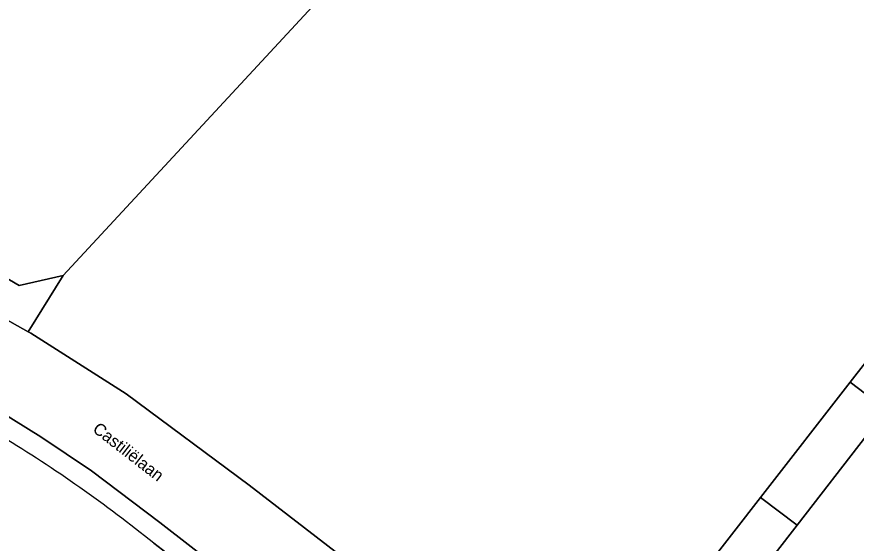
# Model space of a CAD drawing. Extents: x 159451 to 160664, y 388402 to 389723.
# Drawn here: x 160157.1 to 160226.5, y 389335.2 to 389378.7 of the extents above; entities that cross this region are included whole.
import ezdxf

# ---------------------------------------------------------------- set-up
doc = ezdxf.new("R2010")
doc.units = 0
for name, color, linetype in [('IMGEO_Erf', 7, 'Continuous'), ('IMGEO_Groenvoorziening', 7, 'Continuous'), ('IMGEO_Hek', 7, 'Continuous'), ('IMGEO_Openbare_ruimte_label', 7, 'Continuous'), ('IMGEO_Pand', 7, 'Continuous'), ('IMGEO_Rijbaan_lokaal_gesloten', 7, 'Continuous'), ('IMGEO_Voetpad_open', 7, 'Continuous')]:
    doc.layers.add(name, color=color, linetype=linetype)

msp = doc.modelspace()

# ---------------------------------------------------------------- linework, layer by layer
at = {"layer": 'IMGEO_Erf'}
msp.add_lwpolyline([(160227.35, 389344.083), (160221.58, 389336.65), (160214.309, 389327.282), (160216.954, 389325.219), (160212.581, 389319.604), (160206.952, 389323.994), (160206.897, 389324.038), (160205.223, 389321.905), (160205.887, 389321.394), (160222.965, 389308.25), (160226.576, 389313.019)], dxfattribs=at)
at = {"layer": 'IMGEO_Groenvoorziening'}
for points in [[(160039.736, 389411.806), (160043.519, 389377.125), (160045.569, 389377.185), (160095.565, 389378.647), (160130.286, 389372.303), (160147.497, 389362.17), (160157.284, 389356.446), (160160.932, 389357.287), (160193.043, 389391.963)], [(160193.043, 389391.963), (160160.932, 389357.287), (160158.016, 389352.63), (160158.238, 389352.505), (160166.141, 389347.496), (160176.29, 389339.963), (160199.403, 389322.122)], [(160206.952, 389323.994), (160218.568, 389338.933), (160225.978, 389348.463), (160233.375, 389357.976)], [(160221.208, 389296.259), (160220.228, 389294.868), (160218.806, 389296.075), (160218.402, 389295.619), (160215.327, 389298.05), (160215.702, 389298.491), (160170.928, 389333.22), (160168.404, 389335.154)]]:
    msp.add_lwpolyline(points, dxfattribs=at)
msp.add_lwpolyline([(160147.497, 389362.17), (160130.286, 389372.303), (160095.565, 389378.647), (160045.569, 389377.185), (160045.926, 389372.321), (160046.187, 389370.471), (160048, 389370.978), (160058.462, 389372.84), (160069.049, 389373.761), (160080.311, 389374.183), (160093.137, 389373.585), (160094.37, 389373.482), (160107.091, 389371.783), (160119.61, 389368.955), (160127.38, 389366.512), (160143.847, 389360.125), (160149.732, 389357.286), (160158.016, 389352.63), (160160.932, 389357.287), (160157.284, 389356.446)], close=True, dxfattribs=at)
msp.add_arc((160097.271, 389247.24), 113.087, 51.02304, 58.78252, dxfattribs=at)
at = {"layer": 'IMGEO_Hek'}
msp.add_lwpolyline([(160147.497, 389362.17), (160157.284, 389356.446), (160160.932, 389357.287)], dxfattribs=at)
at = {"layer": 'IMGEO_Pand'}
for points in [[(160233.602, 389352.12), (160236.032, 389350.278), (160238.691, 389353.723), (160238.8, 389353.864), (160236.382, 389355.697), (160233.375, 389357.976), (160225.978, 389348.463), (160228.984, 389346.184)], [(160227.35, 389344.083), (160228.984, 389346.184), (160225.978, 389348.463), (160218.568, 389338.933), (160221.58, 389336.65)], [(160221.58, 389336.65), (160218.568, 389338.933), (160206.952, 389323.994), (160212.581, 389319.604), (160216.954, 389325.219), (160214.309, 389327.282)]]:
    msp.add_lwpolyline(points, close=True, dxfattribs=at)
at = {"layer": 'IMGEO_Rijbaan_lokaal_gesloten'}
for points in [[(160230.418, 389298.069), (160221.683, 389304.846), (160220.844, 389305.497), (160202.38, 389319.824), (160199.403, 389322.122), (160176.29, 389339.963), (160166.141, 389347.496), (160158.238, 389352.505), (160158.016, 389352.63), (160149.732, 389357.286), (160143.847, 389360.125), (160127.38, 389366.512), (160119.61, 389368.955), (160107.091, 389371.783), (160094.37, 389373.482), (160093.137, 389373.585)], [(160089.122, 389367.059), (160096.479, 389366.433), (160102.576, 389365.527), (160108.024, 389364.594), (160109.896, 389364.162), (160116.579, 389362.625), (160123.157, 389360.753), (160125.562, 389359.985), (160132.569, 389357.472), (160139.509, 389354.6), (160143.566, 389352.728), (160149.935, 389349.372), (160154.522, 389346.754), (160159.079, 389343.943), (160163.263, 389341.138), (160168.905, 389336.87), (160221.208, 389296.259), (160257.092, 389268.396)]]:
    msp.add_lwpolyline(points, dxfattribs=at)
at = {"layer": 'IMGEO_Voetpad_open'}
for points in [[(160168.905, 389336.87), (160163.263, 389341.138), (160159.079, 389343.943), (160154.522, 389346.754), (160149.935, 389349.372), (160143.566, 389352.728), (160139.509, 389354.6), (160132.569, 389357.472), (160125.562, 389359.985), (160123.157, 389360.753), (160116.579, 389362.625), (160109.896, 389364.162), (160108.024, 389364.594), (160102.576, 389365.527), (160096.479, 389366.433), (160089.122, 389367.059)], [(160168.404, 389335.154), (160170.928, 389333.22), (160215.702, 389298.491), (160215.327, 389298.05), (160218.402, 389295.619), (160218.806, 389296.075), (160220.228, 389294.868), (160221.208, 389296.259), (160168.905, 389336.87)]]:
    msp.add_lwpolyline(points, dxfattribs=at)
msp.add_arc((160097.271, 389247.24), 113.087, 51.02304, 58.78252, dxfattribs=at)

# ---------------------------------------------------------------- texts
at = {"layer": 'IMGEO_Openbare_ruimte_label'}
msp.add_text('Castiliëlaan', height=1, rotation=322.19035, dxfattribs=at).set_placement((160163.284, 389344.437))

doc.saveas('drawing.dxf')
